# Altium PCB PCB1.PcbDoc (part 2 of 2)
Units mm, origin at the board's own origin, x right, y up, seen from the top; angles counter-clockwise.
Board outline 200 x 200.6 mm, 2 copper layers (Top Layer, Bottom Layer); 119 components, 156 nets, 629 pads, 125 vias.
Unrouted connection lines stored in the file: 2.
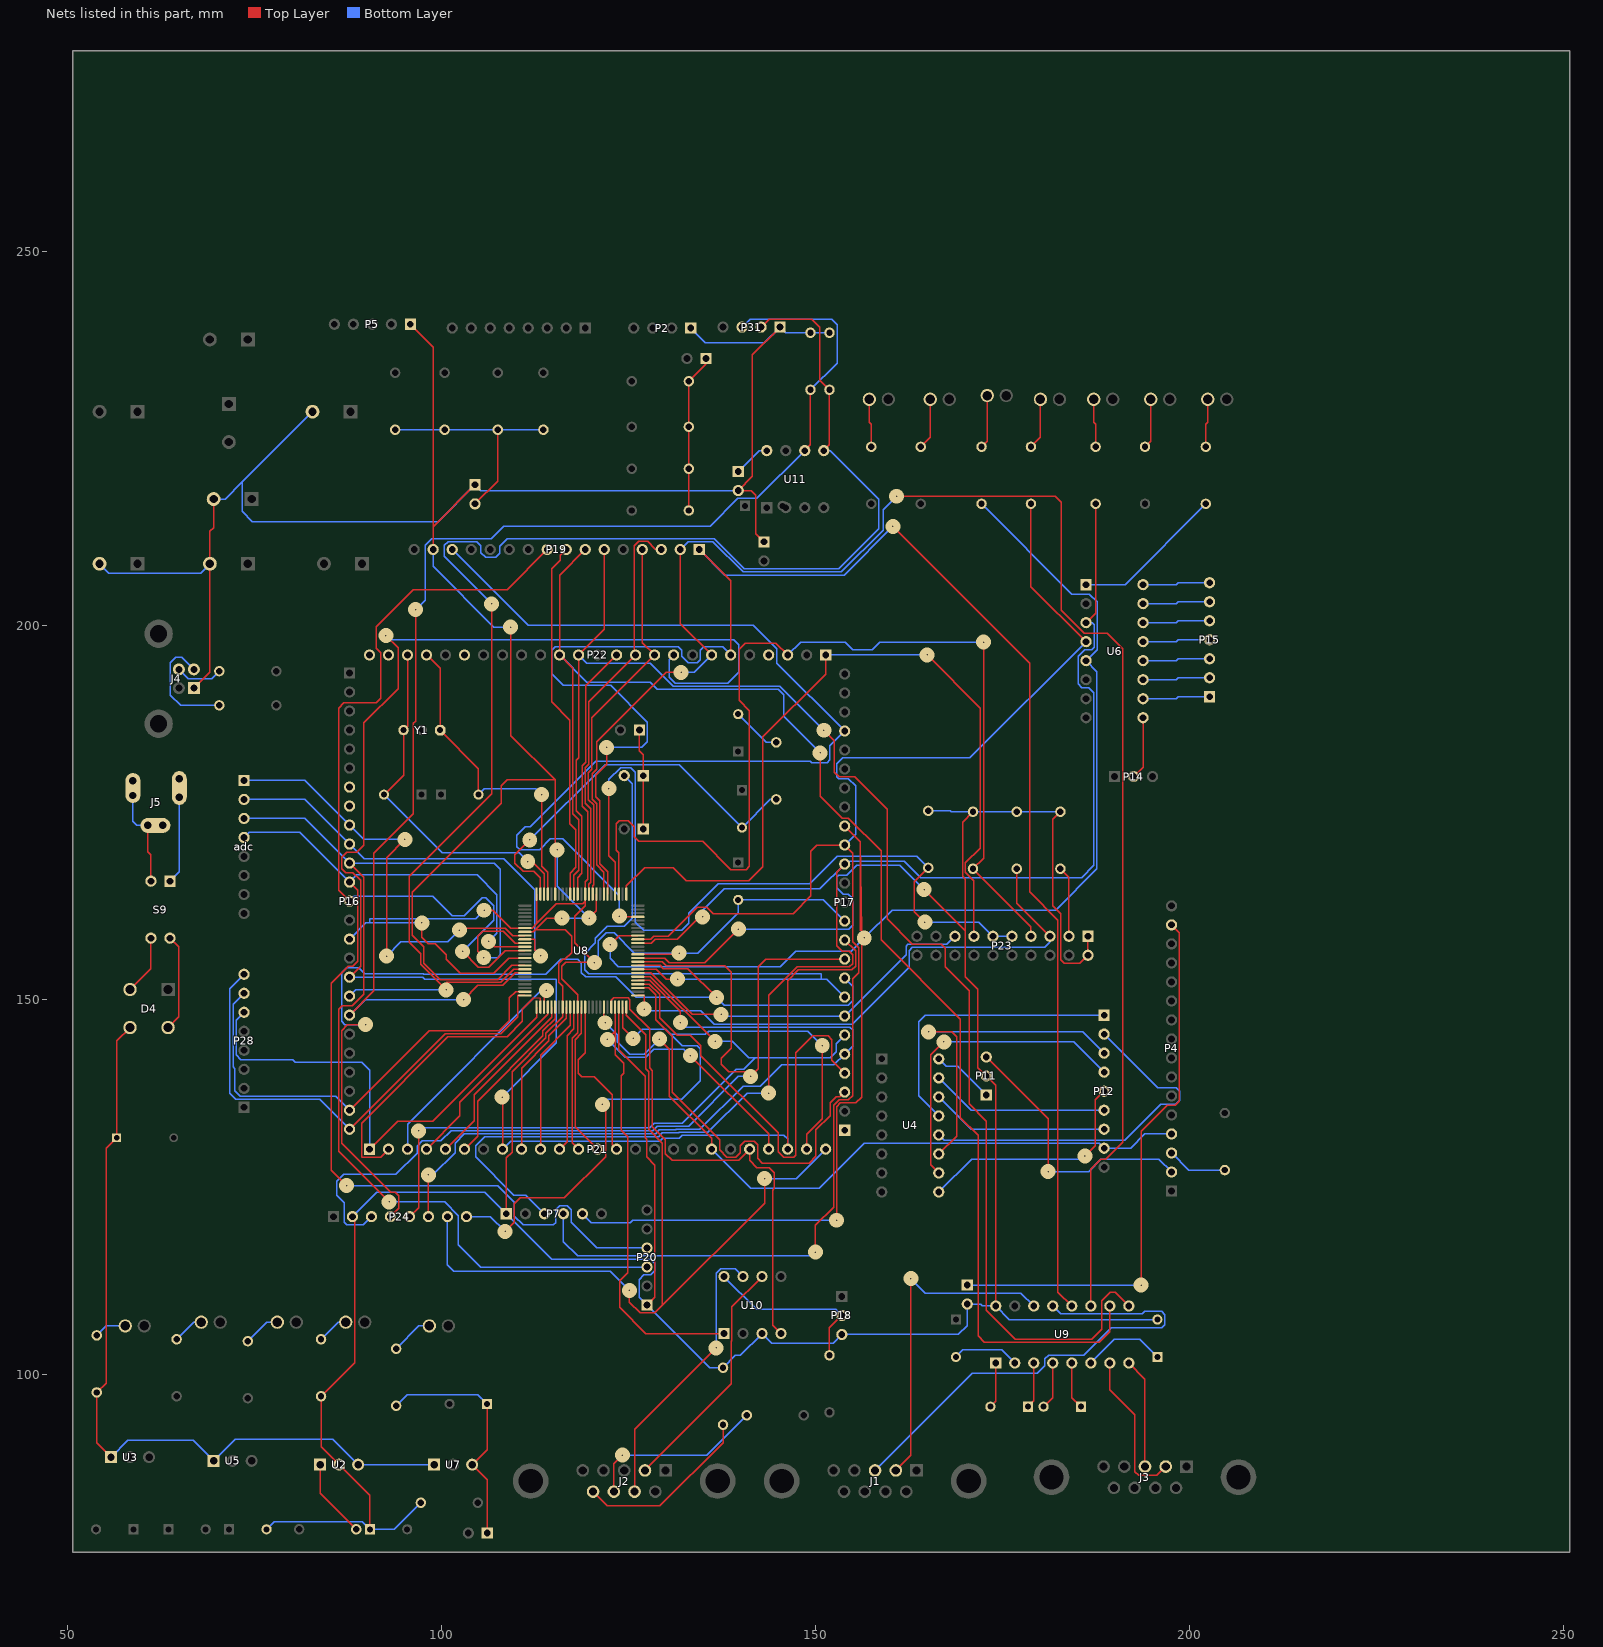
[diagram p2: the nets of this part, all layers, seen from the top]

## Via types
v1: diameter 2, hole 0.2, Top Layer to Bottom Layer, 125 vias

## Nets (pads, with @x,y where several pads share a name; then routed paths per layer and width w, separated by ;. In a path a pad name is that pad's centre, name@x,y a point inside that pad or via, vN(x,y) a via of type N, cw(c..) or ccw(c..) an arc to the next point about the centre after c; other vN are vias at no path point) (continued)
LED2: P7.3 P17.15 R19.1 U6.3 U8.65 | length 217.2
  Top Layer w0.2: U8.65@126.295,157.591 128.102,157.591 128.602,158.091 131.556,158.091 134.551,161.087 v1(134.925,161.087) ; v1(143.764,137.541) 143.764,150.597 147.565,154.398 154.534,154.398 154.974,154.838 154.974,156.058 154.534,156.498 153.619,156.498 152.857,157.26 152.857,167.081 P17.15@153.924,168.148 ; U6.3@186.182,200.406 187.452,201.676 R19.1@187.452,216.281
  Bottom Layer w0.2: P7.3@113.792,121.412 111.328,123.876 109.728,123.876 104.597,129.007 104.597,130.505 105.806,131.714 129.056,131.714 129.559,132.217 131.734,132.217 131.816,132.298 135.654,132.298 140.897,137.541 v1(143.764,137.541) ; v1(134.925,161.087) 134.925,161.95 137.82,164.846 150.622,164.846 P17.15@153.924,168.148 154.305,168.529 161.874,168.529 164.059,166.345 185.598,166.345 187.232,167.979 187.232,191.025 186.538,191.719 185.623,191.719 185.115,192.227 185.115,195.885 186.03,196.799 186.944,196.799 187.249,197.104 187.249,200.152 186.995,200.406 U6.3@186.182,200.406
LED3: P7.4 P17.16 R21.1 U6.4 U8.66 | length 208.6
  Top Layer w0.2: U8.66@126.295,158.091 128,158.091 128.4,158.491 130.34,158.491 134.254,162.405 135.464,162.405 136.346,161.523 147.02,161.523 149.398,163.902 149.398,169.875 150.211,170.688 P17.16@153.924,170.688 154.991,169.621 154.991,157.761 155.774,156.978 155.774,153.598 154.991,152.815 154.991,137.177 154.432,136.618 153.172,136.618 152.451,135.897 152.451,122.301 150.012,119.863 v1(150.012,116.281) ; R21.1@178.816,216.281 178.816,205.232 U6.4@186.182,197.866
  Bottom Layer w0.2: P7.4@116.332,121.412 116.332,117.685 118.244,115.773 149.504,115.773 v1(150.012,116.281) ; P17.16@153.924,170.688 155.397,172.161 155.397,178.613 154.432,179.578 153.128,179.578 152.874,179.832 152.874,181.525 153.67,182.321 170.637,182.321 U6.4@186.182,197.866
LED4: P7.5 P17.17 R22.1 U6.5 U8.67 | length 238.5
  Top Layer w0.2: v1(122.58,157.378) 123.793,158.591 U8.67@126.295,158.591 ; v1(152.857,120.548) 152.857,135.738 153.338,136.218 155.374,136.218 156.174,137.018 156.174,158.267 v1@156.174,159.142 ; P17.17@153.924,173.228 156.032,171.12 ; v1(156.54,158.267) 156.54,158.775 v1@156.174,159.142 ; 156.032,171.12 v1@156.174,159.142 ; 156.032,171.12 156.032,159.283 v1@156.174,159.142
  Bottom Layer w0.2: P7.5@118.872,121.412 120.04,120.244 125.273,120.244 125.578,120.548 v1(152.857,120.548) ; v1(122.58,157.378) 122.58,155.55 123.698,154.432 145.288,154.432 147.371,156.515 154.788,156.515 v1(156.54,158.267) 160.274,162.001 182.118,162.001 187.632,167.515 187.632,193.876 U6.5@186.182,195.326 187.655,196.799 187.655,203.2 186.639,204.216 184.277,204.216 R22.1@172.212,216.281
MISO: P16.24 P28.7 U8.24 | length 61.9
  Top Layer w0.2: P16.24@87.757,135.255 98.376,145.874 107.772,145.874 109.127,147.229 109.127,150.255 109.963,151.091 U8.24@111.195,151.091
  Bottom Layer w0.2: P28.7@73.66,150.876 72.187,149.403 72.187,141.072 72.441,140.818 72.441,137.837 73.152,137.126 85.886,137.126 P16.24@87.757,135.255
MOSI: P16.25 P28.8 U8.25 | length 67.2
  Top Layer w0.2: P16.25@87.757,132.715 100.516,145.474 107.975,145.474 110.24,147.738 110.24,150.591 U8.25@111.195,150.591
  Bottom Layer w0.2: P28.8@73.66,153.416 71.755,151.511 71.755,137.542 72.571,136.726 83.746,136.726 P16.25@87.757,132.715
NetC6_1: C6.1 P13.1 R26.1 U7.3 | length 32.2
  Top Layer w0.2: C6.1@106.132,96.012 106.132,89.876 U7.3@104.14,87.884 106.172,85.852 P13.1@106.172,78.74
  Bottom Layer w0.2: R26.1@93.98,95.758 95.453,97.231 104.913,97.231 C6.1@106.132,96.012
NetC9_2: C9.2 U9.2 | length 9
  Bottom Layer w0.2: C9.2@168.783,102.275 169.734,103.226 174.904,103.226 U9.2@176.657,101.473
NetC10_1: C10.1 U9.3 | length 6.2
  Top Layer w0.2: C10.1@178.395,95.631 179.197,96.433 U9.3@179.197,101.473
NetC10_2: C10.2 U9.1 | length 6.1
  Top Layer w0.2: C10.2@173.395,95.631 174.117,96.353 U9.1@174.117,101.473
NetC11_1: C11.1 U9.5 | length 6.4
  Top Layer w0.2: U9.5@184.277,101.473 184.277,96.861 C11.1@185.507,95.631
NetC11_2: C11.2 U9.4 | length 6.4
  Top Layer w0.2: C11.2@180.507,95.631 181.737,96.861 U9.4@181.737,101.473
NetC12_2: C12.2 R29.1 | length 6.6
  Bottom Layer w0.2: C12.2@139.7,188.174 143.47,184.404 R29.1@144.78,184.404
NetC13_2: C13.2 R29.2 U8.99 | length 52.4
  Top Layer w0.2: v1(111.836,171.374) 109.867,169.404 109.867,168.25 110.938,167.178 112.374,167.178 113.245,166.307 U8.99@113.245,164.141
  Bottom Layer w0.2: v1(111.836,171.374) 121.895,181.432 131.79,181.432 C13.2@140.208,173.014 143.978,176.784 R29.2@144.78,176.784
NetC14_1: C14.1 U9.6 | length 11.2
  Bottom Layer w0.2: U9.6@186.817,101.473 189.967,104.623 193.359,104.623 C14.1@195.707,102.275
NetD2_1: D2.1 R9.2 | length 4.2
  Bottom Layer w0.2: R9.2@83.947,104.648 86.233,106.934 D2.1@87.249,106.934
NetD3_1: D3.1 R14.2 | length 4.3
  Bottom Layer w0.2: R14.2@53.975,105.156 55.245,106.426 D3.1@57.785,106.426
NetD4_2: D4.2 S9.3 | length 8
  Top Layer w0.2: D4.2@58.42,151.384 61.214,154.178 S9.3@61.214,158.242
NetD4_4: D4.4 S9.4 | length 13
  Top Layer w0.2: D4.4@63.5,146.304 64.922,147.726 64.922,157.074 S9.4@63.754,158.242
NetD5_1: D5.1 R17.2 | length 6.5
  Top Layer w0.2: R17.2@202.184,223.901 202.184,226.949 202.438,227.203 D5.1@202.438,230.251
NetD6_1: D6.1 R18.2 | length 6.7
  Top Layer w0.2: R18.2@194.056,223.901 194.818,224.663 D6.1@194.818,230.251
NetD7_1: D7.1 R19.2 | length 6.5
  Top Layer w0.2: D7.1@187.198,230.251 187.198,227.203 187.452,226.949 R19.2@187.452,223.901
NetD8_1: D8.1 R21.2 | length 6.9
  Top Layer w0.2: R21.2@178.816,223.901 180.086,225.171 D8.1@180.086,230.251
NetD9_1: D9.1 R22.2 | length 7.2
  Top Layer w0.2: R22.2@172.212,223.901 172.974,224.663 D9.1@172.974,230.759
NetD10_1: D10.1 R23.2 | length 6.9
  Top Layer w0.2: R23.2@164.084,223.901 165.354,225.171 D10.1@165.354,230.251
NetD11_1: D11.1 R25.2 | length 6.5
  Top Layer w0.2: D11.1@157.226,230.251 157.226,227.203 157.48,226.949 R25.2@157.48,223.901
NetD12_1: D12.1 R24.2 | length 5
  Bottom Layer w0.2: R24.2@74.168,104.394 76.708,106.934 D12.1@78.105,106.934
NetD13_1: D13.1 R20.2 | length 4.2
  Bottom Layer w0.2: R20.2@64.643,104.648 66.929,106.934 D13.1@67.945,106.934
NetD14_1: D14.1 R26.2 | length 5.7
  Bottom Layer w0.2: R26.2@93.98,103.378 97.028,106.426 D14.1@98.425,106.426
NetJ1_2: J1.2 U9.14 | length 44.4
  Top Layer w0.2: J1.2@160.758,87.12 162.763,89.125 v1(162.763,112.751)
  Bottom Layer w0.2: v1(162.763,112.751) 164.694,110.82 177.47,110.82 U9.14@179.197,109.093
NetJ1_3: J1.3 U9.13 | length 64.4
  Bottom Layer w0.2: J1.3@157.988,87.12 170.944,100.076 179.629,100.076 180.67,101.117 180.67,102.006 181.204,102.54 185.903,102.54 189.56,106.197 196.291,106.197 196.698,106.604 196.698,107.95 196.291,108.356 194.031,108.356 193.7,108.026 182.804,108.026 U9.13@181.737,109.093
NetJ2_2: J2.2 U10.6 | length 32.4
  Top Layer w0.2: J2.2@127.23,87.12 138.786,98.676 138.786,104.369 138.862,104.445 138.862,109.017 U10.6@142.875,113.03
NetJ2_7: J2.7 U10.7 | length 38
  Top Layer w0.2: J2.7@125.845,84.28 125.845,92.596 v1(136.728,103.48)
  Bottom Layer w0.2: v1(136.728,103.48) 136.728,113.462 137.363,114.097 139.268,114.097 U10.7@140.335,113.03
NetJ2_8: J2.8 R28.1 | length 24.2
  Top Layer w0.2: J2.8@123.075,84.28 123.075,87.998 v1(124.231,89.154)
  Bottom Layer w0.2: v1(124.231,89.154) 135.509,89.154 R28.1@140.843,94.488
NetJ2_9: J2.9 R27.1 | length 24.1
  Top Layer w0.2: J2.9@120.305,84.28 122.213,82.372 129.235,82.372 137.668,90.805 R27.1@137.668,93.218
NetJ3_2: J3.2 U9.7 | length 20.7
  Top Layer w0.2: U9.7@189.357,101.473 189.357,97.866 192.684,94.539 192.684,86.97 193.192,86.462 195.66,86.462 J3.2@196.826,87.628
NetJ3_3: J3.3 U9.8 | length 14.7
  Top Layer w0.2: U9.8@191.897,101.473 194.056,99.314 J3.3@194.056,87.628
NetJ4_2: J4.2 R31.1 | length 15.5
  Bottom Layer w0.2: J4.2@66.953,194.163 65.333,195.783 64.541,195.783 63.83,195.072 63.83,190.729 65.202,189.357 R31.1@70.358,189.357
NetJ4_3: J4.3 R32.1 | length 6.4
  Bottom Layer w0.2: J4.3@64.953,194.163 66.228,192.888 69.317,192.888 R32.1@70.358,193.929
NetJ5_1: J5.1 J5.1A J5.1B S9.1 | length 15.5
  Top Layer w0.2: J5.1A@65.008,177.058 J5.1@65.008,178.308 J5.1B@65.008,179.558
  Bottom Layer w0.2: S9.1@63.754,165.862 65.008,167.116 J5.1A@65.008,177.058 J5.1@65.008,178.308
NetJ5_2: J5.2 J5.2A J5.2B J5.3 J5.3A J5.3B S9.2 | length 18.3
  Top Layer w0.2: J5.2A@58.808,177.308 J5.2@58.808,178.308 J5.2B@58.808,179.308 ; J5.3A@60.808,173.308 60.808,169.773 61.214,169.367 S9.2@61.214,165.862
  Bottom Layer w0.2: J5.2@58.808,178.308 J5.2A@58.808,177.308 58.808,173.834 59.334,173.308 J5.3A@60.808,173.308 J5.3@61.808,173.308 J5.3B@62.808,173.308
NetP1_2: P1.2 R1.2 R2.2 R3.2 R4.2 | length 31
  Top Layer w0.2: P1.2@104.521,216.281 107.569,219.329 R2.2@107.569,226.187
  Bottom Layer w0.2: R4.2@93.853,226.187 R3.2@100.457,226.187 R2.2@107.569,226.187 R1.2@113.665,226.187
NetP4_2: P4.2 P11.3 | length 36.6
  Top Layer w0.2: P11.3@172.847,142.367 181.102,134.112 v1(181.102,127.051)
  Bottom Layer w0.2: v1(181.102,127.051) 186.526,127.051 188.16,128.685 195.927,128.685 P4.2@197.612,127
NetP4_3: P4.3 R8.1 | length 8.1
  Bottom Layer w0.2: P4.3@197.612,129.54 199.898,127.254 R8.1@204.724,127.254
NetP4_15: P4.15 P10.1 | length 74.5
  Top Layer w0.2: v1(193.548,111.887) 193.548,132.41 197.028,135.89 198.069,135.89 198.662,136.483 198.662,158.97 P4.15@197.612,160.02
  Bottom Layer w0.2: P10.1@170.307,111.887 v1(193.548,111.887)
NetP8_1: P8.1 R10.1 R11.1 R12.1 R13.1 | length 21.3
  Top Layer w0.2: R10.1@133.096,215.392 R11.1@133.096,220.98 R12.1@133.096,226.568 R13.1@133.096,232.664 135.382,234.95 P8.1@135.382,235.712
NetP11_1: P11.1 U4.16 | length 8.3
  Bottom Layer w0.2: U4.16@166.497,142.113 167.488,141.122 169.012,141.122 P11.1@172.847,137.287
NetP12_1: P12.1 U4.13 | length 38.8
  Bottom Layer w0.2: U4.13@166.497,134.493 163.805,137.185 163.805,147.041 164.719,147.955 P12.1@188.595,147.955
NetP12_2: P12.2 U4.12 | length 49.1
  Bottom Layer w0.2: U4.12@166.497,131.953 167.21,131.24 191.318,131.24 196.148,136.07 198.198,136.07 198.679,136.55 198.679,137.77 198.222,138.227 195.783,138.227 P12.2@188.595,145.415
NetP12_3: P12.3 U4.11 | length 45.3
  Top Layer w0.2: v1(165.125,145.72) 168.25,145.72 168.885,145.085 168.885,131.801 U4.11@166.497,129.413
  Bottom Layer w0.2: v1(165.125,145.72) 185.75,145.72 P12.3@188.595,142.875
NetP12_4: P12.4 U4.10 | length 41.8
  Top Layer w0.2: U4.10@166.497,126.873 165.43,127.94 165.43,142.646 v1(167.183,144.399)
  Bottom Layer w0.2: v1(167.183,144.399) 184.531,144.399 P12.4@188.595,140.335
NetP12_5: P12.5 U4.9 | length 31.2
  Top Layer w0.2: v1(186.03,129.134) 187.427,130.531 187.427,136.627 P12.5@188.595,137.795
  Bottom Layer w0.2: U4.9@166.497,124.333 170.891,128.727 185.623,128.727 v1(186.03,129.134)
NetP12_6: P12.6 U4.15 | length 23.9
  Bottom Layer w0.2: U4.15@166.497,139.573 170.815,135.255 P12.6@188.595,135.255
NetP12_7: P12.7 U4.14 | length 23.9
  Bottom Layer w0.2: U4.14@166.497,137.033 170.815,132.715 P12.7@188.595,132.715
NetP14_2: P14.2 U6.9 | length 8.4
  Top Layer w0.2: P14.2@192.532,179.832 193.802,181.102 U6.9@193.802,187.706
NetP15_1: P15.1 U6.10 | length 9
  Bottom Layer w0.2: U6.10@193.802,190.246 198.247,190.246 198.501,190.5 P15.1@202.692,190.5
NetP15_2: P15.2 U6.11 | length 9
  Bottom Layer w0.2: U6.11@193.802,192.786 198.247,192.786 198.501,193.04 P15.2@202.692,193.04
NetP15_3: P15.3 U6.12 | length 9
  Bottom Layer w0.2: U6.12@193.802,195.326 198.247,195.326 198.501,195.58 P15.3@202.692,195.58
NetP15_4: P15.4 U6.13 | length 9
  Bottom Layer w0.2: U6.13@193.802,197.866 198.247,197.866 198.501,198.12 P15.4@202.692,198.12
NetP15_5: P15.5 U6.14 | length 9
  Bottom Layer w0.2: U6.14@193.802,200.406 198.247,200.406 198.501,200.66 P15.5@202.692,200.66
NetP15_6: P15.6 U6.15 | length 9
  Bottom Layer w0.2: U6.15@193.802,202.946 198.247,202.946 198.501,203.2 P15.6@202.692,203.2
NetP15_7: P15.7 U6.16 | length 9
  Bottom Layer w0.2: U6.16@193.802,205.486 198.247,205.486 198.501,205.74 P15.7@202.692,205.74
NetP18_2: P18.2 R30.2 U10.8 | length 23.9
  Top Layer w0.2: R30.2@151.892,102.489 151.892,106.172 P18.2@153.543,107.823
  Bottom Layer w0.2: U10.8@137.795,113.03 142.189,108.636 152.73,108.636 P18.2@153.543,107.823
NetP23_3: P23.3 R36.1 | length 9.5
  Top Layer w0.2: R36.1@182.753,167.513 183.896,166.37 P23.3@183.896,158.496
NetP23_5: P23.5 R35.1 U8.51 | length 75.2
  Top Layer w0.2: U8.51@126.295,150.591 127.127,150.591 v1(127.127,148.768) ; R35.1@176.911,167.513 176.911,162.941 P23.5@181.356,158.496
  Bottom Layer w0.2: v1(127.127,148.768) 127.356,148.539 134.717,148.539 136.5,146.757 154.944,146.757 162.526,154.339 162.526,156.566 162.966,157.006 180.679,157.006 181.356,157.683 P23.5@181.356,158.496
NetP23_9: P23.9 P23.11 R33.1 U8.79 | length 106.3
  Top Layer w0.2: v1(122.403,178.232) 122.403,169.244 123.245,168.402 U8.79@123.245,164.141 ; v1(164.643,160.376) 163.22,161.798 163.22,165.76 R33.1@165.1,167.64
  Bottom Layer w0.2: v1(122.403,178.232) 122.403,179.451 123.977,181.026 125.349,181.026 125.933,180.442 125.933,160.401 127.051,159.283 132.14,159.283 133.101,160.244 133.101,161.56 137.06,165.52 149.242,165.52 152.921,169.198 163.542,169.198 R33.1@165.1,167.64 ; v1(164.643,160.376) 171.856,160.376 P23.11@173.736,158.496 P23.9@176.276,158.496
NetP27_1: P27.1 P30.1 P33.1 | length 13.4
  Top Layer w0.2: P33.1@126.492,186.055 126.492,183.261 127,182.753 P27.1@127,179.959 P30.1@127,172.847
NetP32_1: P32.1 U11.8 | length 5
  Bottom Layer w0.2: P32.1@139.7,220.599 142.494,223.393 U11.8@143.51,223.393
NetR15_2: R15.2 U2.1 | length 10.6
  Top Layer w0.2: U2.1@83.82,87.884 83.82,84.074 R15.2@88.646,79.248
NetR17_1: R17.1 U6.1 | length 20.5
  Bottom Layer w0.2: U6.1@186.182,205.486 191.389,205.486 R17.1@202.184,216.281
NRST: P17.7 P23.15 U8.57 | length 49.8
  Top Layer w0.2: U8.57@126.295,153.591 128.021,153.591 133.555,148.057 v1(137.414,148.057)
  Bottom Layer w0.2: v1(137.414,148.057) 137.643,147.828 P17.7@153.924,147.828 162.126,156.03 162.126,157.175 162.357,157.406 167.566,157.406 P23.15@168.656,158.496
PA0/PGMEN0/RXD0: P19.1 P22.6 U8.81 U9.12 | length 235.3
  Top Layer w0.2: v1(122.098,183.744) 122.098,181.467 120.629,179.998 120.629,177.175 121.195,176.609 121.195,168.198 122.245,167.148 U8.81@122.245,164.141 ; P19.1@134.493,210.185 138.684,205.994 P22.6@138.684,196.088 ; v1(160.376,213.258) 178.638,194.996 178.638,164.44 182.423,160.655 182.423,110.947 U9.12@184.277,109.093
  Bottom Layer w0.2: v1(122.098,183.744) 126.797,183.744 127.559,184.506 127.559,187.122 122.657,192.024 116.307,192.024 114.757,193.573 114.757,196.698 115.214,197.155 131.674,197.155 132.131,196.698 132.131,195.91 133.003,195.038 134.214,195.038 134.654,195.478 134.654,196.698 135.111,197.155 137.617,197.155 P22.6@138.684,196.088 ; P19.1@134.493,210.185 137.922,206.756 153.873,206.756 v1(160.376,213.258)
PA1/PGMEN1/TXD0: P19.2 P22.7 U8.82 U9.11 | length 231.1
  Top Layer w0.2: U8.82@121.745,164.141 121.745,167.08 120.795,168.03 120.795,176.209 120.18,176.823 120.18,180.208 120.766,180.794 120.766,184.469 130.048,193.751 v1(132.08,193.751) ; P19.2@131.953,210.185 131.953,200.279 P22.7@136.144,196.088 ; v1(160.858,217.297) 182.067,217.297 182.88,216.484 182.88,202.032 185.928,198.984 189.027,198.984 191.059,196.952 191.059,130.962 188.781,128.685 188.16,128.685 186.817,127.342 U9.11@186.817,109.093
  Bottom Layer w0.2: P19.2@131.953,210.185 133.003,211.235 136.306,211.235 140.353,207.188 153.492,207.188 159.055,212.75 159.055,215.494 v1(160.858,217.297) ; v1(132.08,193.751) 133.807,193.751 P22.7@136.144,196.088
"PA2 3/PGMD11/TD": P17.5 P24.6 U8.55 | length 104.7
  Top Layer w0.2: P24.6@98.298,121.031 v1(98.298,126.619) ; U8.55@126.295,152.591 127.89,152.591 131.978,148.502 v1(131.978,146.964)
  Bottom Layer w0.2: v1(98.298,126.619) 98.908,126.619 101.854,129.565 101.854,130.861 103.107,132.114 128.656,132.114 129.159,132.617 131.334,132.617 131.416,132.698 134.578,132.698 140.356,138.476 142.651,138.476 145.481,141.307 152.483,141.307 P17.5@153.924,142.748 154.991,143.815 154.991,145.999 154.633,146.357 132.586,146.357 v1(131.978,146.964)
PA2/SCK0: P19.3 P22.11 U8.86 | length 54.1
  Top Layer w0.2: U8.86@119.745,164.141 119.745,165.45 119.995,165.7 119.995,175.56 119.268,176.287 119.268,181.026 119.742,181.5 119.742,189.846 P22.11@125.984,196.088 125.806,196.266 125.806,210.668 126.39,211.252 127.61,211.252 128.575,210.287 128.575,210.185 P19.3@129.413,210.185
PA3/RTS0: P19.4 P22.10 U8.85 | length 50.8
  Top Layer w0.2: U8.85@120.245,164.141 120.245,165.235 120.395,165.385 120.395,176.043 119.668,176.77 119.668,180.374 120.142,180.848 120.142,187.706 P22.10@128.524,196.088 126.873,197.739 P19.4@126.873,210.185
"PA5/PGMRDY/RX D 1": P19.6 P22.14 U8.89 U9.9 | length 201.3
  Top Layer w0.2: U8.89@118.245,164.141 118.245,166.35 118.795,166.9 118.795,174.518 118.028,175.285 118.028,182.016 118.364,182.352 P22.14@118.364,196.088 121.793,199.517 P19.6@121.793,210.185 ; v1(151.13,186.03) 152.527,184.633 152.527,180.442 153.187,179.781 155.245,179.781 159.58,175.446 159.58,160.816 162.966,157.429 166.827,157.429 167.386,156.87 167.386,154.405 170.561,151.23 170.561,136.119 172.872,133.807 172.872,108.509 176.712,104.669 186.969,104.669 188.29,105.99 188.29,109.804 189.382,110.896 190.094,110.896 U9.9@191.897,109.093
  Bottom Layer w0.2: P22.14@118.364,196.088 119.482,194.97 127.948,194.97 130.989,191.928 145.231,191.928 v1(151.13,186.03)
"PA6/PGMNOE/T X D1": P19.7 P22.15 U8.90 U9.10 | length 199.8
  Top Layer w0.2: U8.90@117.745,164.141 117.745,166.65 118.395,167.3 118.395,174.06 117.594,174.861 117.594,194.318 P22.15@115.824,196.088 115.824,206.756 P19.7@119.253,210.185 ; v1(150.647,183.007) 150.647,177.241 153.594,174.295 154.432,174.295 158.78,169.947 158.78,158.009 169.393,147.396 169.393,134.264 171.78,131.877 171.78,105.08 172.593,104.267 187.96,104.267 189.357,105.664 U9.10@189.357,109.093
  Bottom Layer w0.2: P22.15@115.824,196.088 119.482,192.43 127.969,192.43 128.871,191.528 145.024,191.528 145.779,190.773 145.779,187.875 v1(150.647,183.007)
PA7/PGMNVALID/SCK1: P19.8 U8.91 | length 48.5
  Top Layer w0.2: P19.8@116.713,210.185 115.913,209.385 115.913,208.735 114.757,207.579 114.757,189.809 117.194,187.373 117.194,173.501 117.995,172.7 117.995,167.7 117.245,166.95 U8.91@117.245,164.141
PA8/PGMM0/RTS1: P16.13 P19.9 U8.13 | length 109.5
  Top Layer w0.2: P16.13@87.757,163.195 86.307,164.645 86.307,188.999 86.993,189.685 91.311,189.685 91.897,190.271 91.897,196.384 91.308,196.972 91.308,199.869 96.265,204.826 108.814,204.826 P19.9@114.173,210.185 ; v1(102.87,156.464) 104.983,154.351 106.351,154.351 108.591,156.591 U8.13@111.195,156.591
  Bottom Layer w0.2: P16.13@87.757,163.195 88.392,163.83 98.857,163.83 101.452,161.235 103.094,161.235 105.486,163.627 105.969,163.627 107.036,162.56 107.036,160.63 v1(102.87,156.464)
"PA10/PGMM2/TW D": P16.18 P31.2 R37.1 U8.18 U11.5 | length 199.5
  Top Layer w0.2: v1(106.756,202.921) 106.756,177.546 95.707,166.497 95.707,157.713 97.255,156.166 97.255,154.739 v1(100.66,151.333) 100.66,152.319 107.955,152.319 109.726,154.091 U8.18@111.195,154.091 ; P31.2@142.748,239.903 143.815,240.97 149.555,240.97 150.622,239.903 150.622,232.791 R37.1@151.892,231.521 151.892,224.155 U11.5@151.13,223.393
  Bottom Layer w0.2: P16.18@87.757,150.495 88.595,151.333 v1(100.66,151.333) ; v1(106.756,202.921) 100.406,209.271 100.406,210.718 100.923,211.235 104.741,211.235 105.283,210.693 105.283,209.779 105.943,209.118 107.29,209.118 107.823,209.652 107.823,210.642 108.816,211.635 136.472,211.635 140.513,207.594 153.111,207.594 158.496,212.979 158.496,216.891 151.994,223.393 U11.5@151.13,223.393
"PA11/PGMM3/TW CK": P16.19 P31.3 R38.1 U8.19 U11.6 | length 180.8
  Top Layer w0.2: P16.19@87.757,147.955 91.004,151.202 91.004,169.591 96.291,174.879 96.291,186.944 96.594,187.247 v1(96.594,202.159) ; v1(102.99,150.033) 104.876,151.919 108.231,151.919 109.903,153.591 U8.19@111.195,153.591 ; U11.6@148.59,223.393 149.352,224.155 R38.1@149.352,231.521
  Bottom Layer w0.2: P16.19@87.757,147.955 89.835,150.033 v1(102.99,150.033) ; v1(96.594,202.159) 97.866,203.431 97.866,210.752 98.749,211.635 106.711,211.635 108.385,213.309 135.956,213.309 139.649,217.002 142.199,217.002 U11.6@148.59,223.393 ; P31.3@140.208,239.903 141.275,240.97 152.171,240.97 152.908,240.233 152.908,235.077 R38.1@149.352,231.521
PA18/PGMD6/SPI0_SPCK: P21.1 P28.6 U8.26 | length 66.4
  Top Layer w0.2: P21.1@90.424,130.048 94.173,133.797 98.887,133.797 112.745,147.656 U8.26@112.745,149.041
  Bottom Layer w0.2: P28.6@73.66,148.336 72.593,147.269 72.593,142.646 73.228,142.011 80.137,142.011 80.518,141.63 89.408,141.63 90.424,140.614 P21.1@90.424,130.048
PA19/PGMD7/CANRX: P21.21 U8.46 U10.4 | length 65.9
  Top Layer w0.2: U8.46@122.745,149.041 122.745,149.962 123.05,150.266 124.968,150.266 125.197,150.038 125.197,148.768 127.844,146.12 127.844,140.906 128.232,140.519 128.232,133.032 129.974,131.289 129.974,129.462 130.861,128.575 139.751,128.575 P21.21@141.224,130.048 141.224,128.548 142.191,127.581 143.866,127.581 144.541,126.906 144.541,124.803 144.325,124.587 144.325,106.5 U10.4@145.415,105.41
PA20/PGMD8/CANTX: P21.22 U8.47 U10.1 | length 88.1
  Top Layer w0.2: v1(122.199,144.729) 123.245,145.775 ; U8.47@123.245,149.041 123.245,145.775 ; v1(133.299,142.545) 143.764,132.08 P21.22@143.764,130.048 ; U10.1@137.795,105.41 127.346,105.41 123.841,108.915 123.841,112.47 124.917,113.546 124.917,131.699 124.054,132.563 124.054,139.852 124.384,140.183 124.384,141.508 123.245,142.646 123.245,144.729 123.245,145.775
  Bottom Layer w0.2: v1(122.199,144.729) 124.585,142.343 127.354,142.343 128.417,143.407 132.437,143.407 v1(133.299,142.545)
PA21/PGMD9/TF: P21.24 P24.8 U8.49 | length 102
  Top Layer w0.2: v1(108.547,119.062) 109.779,120.294 109.779,122.733 110.592,123.546 116.459,123.546 121.971,129.057 121.971,135.611 v1(121.539,136.042) ; U8.49@124.245,149.041 124.245,146.265 v1(125.654,144.856) ; P21.24@148.844,130.048 148.844,132.029 150.927,134.112 v1(150.927,143.891)
  Bottom Layer w0.2: P24.8@103.378,121.031 106.578,121.031 v1(108.547,119.062) ; v1(121.539,136.042) 122.229,136.733 132.135,136.733 134.62,139.217 134.62,143.459 134.214,143.866 132.232,143.866 130.704,145.394 ; v1(125.654,144.856) 126.852,146.055 130.043,146.055 130.704,145.394 ; v1(150.927,143.891) 148.987,145.831 135.738,145.831 135.301,145.394 130.704,145.394
PA22/PGMD10/TK: P21.25 P24.7 U8.50 | length 113.4
  Top Layer w0.2: U8.50@124.745,149.041 124.745,147.924 127.356,145.313 127.356,140.767 127.711,140.411 127.711,132.724 129.574,130.861 129.574,109.178 ; v1(125.146,111.176) 125.146,109.618 126.594,108.17 128.566,108.17 129.57,109.174 ; v1(143.231,126.111) 143.231,122.834 129.574,109.178 ; 129.57,109.174 129.574,109.178 ; 129.57,109.174 129.574,109.169 129.574,109.178
  Bottom Layer w0.2: P24.7@100.838,121.031 100.838,114.605 101.702,113.741 122.58,113.741 v1(125.146,111.176) ; v1(143.231,126.111) 147.447,126.111 P21.25@151.384,130.048
PA24/PGMD12/RD: P17.6 P24.5 U8.56 | length 95
  Top Layer w0.2: P24.5@95.758,121.031 96.977,122.25 v1(96.977,132.486) ; U8.56@126.295,153.091 127.955,153.091 v1(136.601,144.445)
  Bottom Layer w0.2: v1(96.977,132.486) 97.411,132.92 127.862,132.92 128.47,133.528 132.232,133.528 139.421,140.716 140.441,140.716 141.965,142.24 ; v1(136.601,144.445) 138.901,144.445 141.106,142.24 141.965,142.24 ; P17.6@153.924,145.288 152.781,144.145 152.781,143.053 151.968,142.24 141.965,142.24
PA25/PGMD13/RK: P17.9 P24.4 U8.59 | length 131.4
  Top Layer w0.2: v1(89.916,146.685) 87.478,146.685 86.69,145.898 86.69,130.852 93.261,124.281 93.878,124.281 94.345,123.815 94.345,122.158 P24.4@93.218,121.031 ; U8.59@126.295,154.591 129.266,154.591 129.701,154.156 132.976,154.156 v1(136.81,150.322)
  Bottom Layer w0.2: v1(89.916,146.685) 87.122,146.685 86.69,147.117 86.69,153.619 87.376,154.305 88.98,154.305 89.803,153.482 97.6,153.482 97.665,153.418 113.987,153.418 115.967,155.397 118.262,155.397 118.745,154.915 118.745,153.619 119.304,153.06 123.317,153.06 126.06,150.317 v1@136.81,150.317 ; v1(136.81,150.322) v1@136.81,150.317 ; P17.9@153.924,152.908 154.991,151.841 154.991,149.86 154.432,149.301 137.831,149.301 v1@136.81,150.317
PA26/PGMD14/RF: P17.10 P24.3 U8.60 | length 129.6
  Top Layer w0.2: U8.60@126.295,155.091 129.566,155.091 130.101,154.556 137.898,154.556 138.735,153.719 138.735,143.535 137.414,142.215 137.414,141.427 138.455,140.386 141.351,140.386 v1(141.351,139.776) 142.342,140.767 142.342,154.432 143.358,155.448 P17.10@153.924,155.448
  Bottom Layer w0.2: P24.3@90.678,121.031 89.611,119.964 87.376,119.964 87.071,120.269 87.071,122.876 86.063,123.884 86.063,125.776 86.97,126.682 93.942,126.682 96.774,129.515 96.774,130.454 97.46,131.14 99.949,131.14 101.329,132.52 128.262,132.52 128.863,133.121 133.071,133.121 139.725,139.776 v1(141.351,139.776)
PB4/ECRS: P17.4 U8.54 | length 59.6
  Top Layer w0.2: U8.54@126.295,152.091 127.824,152.091 129.178,150.737 129.178,147.638 131.535,145.281 133.269,145.281 134.704,143.845 134.704,142.545 145.034,132.215 145.034,129.718 145.754,128.998 147.117,128.998 147.354,129.235 147.354,142.918 149.627,145.191 151.714,145.191 152.227,144.678 152.227,141.905 P17.4@153.924,140.208
PB5/ERX0: P21.9 U8.34 | length 21.5
  Top Layer w0.2: P21.9@110.744,130.048 110.744,140.886 114.409,144.551 114.409,145.203 116.745,147.539 U8.34@116.745,149.041
PB6/ERX1: P21.6 U8.31 | length 24
  Top Layer w0.2: P21.6@103.124,130.048 104.88,131.804 104.88,136.446 113.609,145.175 113.609,145.846 115.245,147.482 U8.31@115.245,149.041
PB7/ERXER: P21.13 U8.38 | length 20.6
  Top Layer w0.2: U8.38@118.745,149.041 118.745,145.517 117.909,144.68 117.909,133.043 P21.13@120.904,130.048
PB8/EMDC: P21.3 U8.28 | length 31.7
  Top Layer w0.2: U8.28@113.745,149.041 113.745,150.931 v1(114.071,151.257)
  Bottom Layer w0.2: P21.3@95.504,130.048 95.504,133.391 113.37,151.257 v1(114.071,151.257)
PB9/EMDIO: P21.2 U8.27 | length 41.6
  Top Layer w0.2: P21.2@92.964,130.048 91.897,128.981 89.357,128.981 89.357,133.528 100.903,145.074 108.799,145.074 110.868,147.143 110.868,148.739 112.395,150.266 113.245,150.241 U8.27@113.245,149.041
PB10/ETX2: P4.4 P12.8 P21.19 U8.44 | length 97.3
  Top Layer w0.2: U8.44@121.745,149.041 121.745,147.114 v1(121.92,146.939) ; v1(129.159,144.755) 130.484,143.429 130.484,137.133 136.144,131.473 P21.19@136.144,130.048
  Bottom Layer w0.2: v1(121.92,146.939) 123.541,145.318 123.541,144.374 125.171,142.743 127.148,142.743 v1(129.159,144.755) ; P21.19@136.144,130.048 141.389,124.803 150.533,124.803 156.57,130.84 187.93,130.84 P12.8@188.595,130.175 192.151,130.175 194.056,132.08 P4.4@197.612,132.08
PB12/ETXER: P21.14 U8.39 | length 22.5
  Top Layer w0.2: U8.39@119.245,149.041 119.245,142.922 118.309,141.986 118.309,140.208 118.796,139.721 120.451,139.721 122.839,137.333 122.839,130.653 P21.14@123.444,130.048
PB13/ERX2: P21.5 U8.30 | length 24.9
  Top Layer w0.2: P21.5@100.584,130.048 104.411,133.875 104.411,137.316 114.745,147.65 U8.30@114.745,149.041
PB14/ERX3: P21.4 U8.29 | length 25.7
  Top Layer w0.2: P21.4@98.044,130.048 102.498,134.502 102.498,136.32 114.245,148.066 U8.29@114.245,149.041
PB15/ERXDV/ECRSDV: P21.10 U8.35 | length 20.6
  Top Layer w0.2: P21.10@113.284,130.048 113.284,142.626 117.245,146.587 U8.35@117.245,149.041
PB16/ECOL: P17.3 U8.53 | length 54.8
  Top Layer w0.2: U8.53@126.295,151.591 127.758,151.591 128.688,150.661 128.688,147.327 130.884,145.131 130.884,137.661 137.211,131.334 137.211,129.946 138.176,128.981 139.395,128.981 139.954,129.54 139.954,130.505 140.547,131.098 141.834,131.098 142.274,130.658 142.274,128.829 142.905,128.198 149.178,128.198 150.089,129.108 150.089,132.642 151.992,134.545 151.992,136.224 152.806,137.039 153.295,137.039 P17.3@153.924,137.668
PB17/ERXCK: P21.11 U8.36 | length 19.8
  Top Layer w0.2: P21.11@115.824,130.048 116.816,131.04 116.816,145.197 117.745,146.126 U8.36@117.745,149.041
PB26/TIOB1: P17.22 P19.14 U8.72 | length 138.8
  Top Layer w0.2: v1(123.825,161.188) 123.922,161.091 U8.72@126.295,161.091
  Bottom Layer w0.2: P19.14@101.473,210.185 111.608,200.05 141.707,200.05 144.854,196.903 144.854,194.998 P17.22@153.924,185.928 151.947,183.951 151.947,182.067 151.587,181.707 149.53,181.707 149.347,181.889 120.675,181.889 111.912,173.126 111.227,173.126 110.13,172.03 110.13,170.464 110.541,170.053 113.145,170.053 114.592,171.5 116.23,171.5 123.825,163.906 v1(123.825,161.188)
PB27/AD0/TIOA2: adc.1 P16.9 U8.9 | length 61.8
  Top Layer w0.2: v1(92.71,155.854) 92.71,169.012 v1(95.148,171.45) ; v1(102.438,159.309) 102.716,159.586 108.591,159.586 109.586,158.591 U8.9@111.195,158.591
  Bottom Layer w0.2: adc.1@73.66,179.324 81.788,179.324 P16.9@87.757,173.355 89.662,171.45 v1(95.148,171.45) ; v1(92.71,155.854) 94.616,157.761 100.89,157.761 v1(102.438,159.309)
PB28/AD1/TIOB2: adc.2 P16.10 U8.10 | length 56.8
  Top Layer w0.2: U8.10@111.195,158.091 112.444,158.091 112.492,158.043 112.492,156.672 v1(113.284,155.88)
  Bottom Layer w0.2: adc.2@73.66,176.784 81.788,176.784 P16.10@87.757,170.815 89.713,168.859 108.38,168.859 112.492,164.747 112.492,156.672 v1(113.284,155.88)
PB29/AD2/PCK1: adc.3 P16.11 P20.3 U8.11 | length 152.7
  Top Layer w0.2: P16.11@87.757,168.275 89.624,166.408 89.624,150.762 88.087,149.225 86.766,149.225 86.284,148.742 86.284,129.743 v1(93.04,122.987) ; v1(105.689,155.651) 104.877,156.464 104.877,158.496 105.567,159.186 108.301,159.186 109.896,157.591 U8.11@111.195,157.591
  Bottom Layer w0.2: adc.3@73.66,174.244 81.788,174.244 P16.11@87.757,168.275 107.086,168.275 107.925,167.437 107.925,156.032 107.544,155.651 v1(105.689,155.651) ; v1(93.04,122.987) 100.457,122.987 102.311,121.133 102.311,117.272 105.283,114.3 P20.3@127.508,114.3
PB30/AD3/PCK2: adc.4 P16.12 P20.4 U8.12 | length 142.6
  Top Layer w0.2: v1(87.363,125.184) 85.293,127.254 85.293,152.222 87.579,154.508 88.189,154.508 88.824,155.143 88.824,164.668 P16.12@87.757,165.735 ; v1(106.35,157.81) 107.069,157.091 U8.12@111.195,157.091
  Bottom Layer w0.2: adc.4@73.66,171.704 74.377,172.421 81.071,172.421 P16.12@87.757,165.735 88.722,166.7 104.8,166.7 107.442,164.059 107.442,158.902 v1(106.35,157.81) ; v1(87.363,125.184) 107.531,125.184 109.779,122.936 109.779,121.107 110.966,119.92 115.011,119.92 115.282,120.191 115.282,121.92 115.824,122.462 116.84,122.462 117.382,121.92 117.382,120.26 120.802,116.84 P20.4@127.508,116.84
PLLRC: P22.24
TCK: P22.4
TDI: P17.1
TDO: P22.1 P23.13 U8.76 | length 109
  Top Layer w0.2: U8.76@124.745,164.141 124.745,165.218 127.197,167.67 130.988,167.67 132.75,165.907 141.092,165.907 143.002,167.818 143.002,185.139 151.384,193.521 P22.1@151.384,196.088 ; v1(164.948,196.088) 172.069,188.967 172.069,170.291 170.069,168.291 170.069,167.04 171.196,165.913 P23.13@171.196,158.496
  Bottom Layer w0.2: P22.1@151.384,196.088 v1(164.948,196.088)
TMS: P22.3 P23.7 R34.1 U8.78 | length 139.1
  Top Layer w0.2: U8.78@123.745,164.141 123.745,169.647 123.393,169.998 123.393,173.533 123.8,173.939 124.968,173.939 125.781,173.126 125.781,171.78 126.39,171.171 134.925,171.171 138.709,167.386 140.741,167.386 141.199,167.843 141.199,188.646 139.802,190.043 139.802,196.85 140.614,197.663 144.729,197.663 P22.3@146.304,196.088 ; v1(172.491,197.815) 172.491,168.935 R34.1@171.069,167.513 178.816,159.766 P23.7@178.816,158.496
  Bottom Layer w0.2: P22.3@146.304,196.088 148.031,197.815 153.992,197.815 154.991,196.817 157.591,196.817 158.589,197.815 v1(172.491,197.815)
TST: P17.8 P27.2 U8.58 | length 92.1
  Top Layer w0.2: U8.58@126.295,154.091 128.771,154.091 130.08,152.782 v1(131.597,152.782)
  Bottom Layer w0.2: P27.2@124.46,179.959 125.527,178.892 125.527,160.934 124.46,159.868 122.225,159.868 120.603,158.246 120.603,157.63 119.159,156.185 119.159,154.026 119.701,153.483 131.597,153.483 150.809,153.483 150.809,152.782 ; v1(131.597,152.782) 150.809,152.782 ; P17.8@153.924,150.368 151.51,152.782 150.809,152.782
VCC: C2.1 C14.2 C15.2 J4.1 P1.1 P2.1 P5.1 P7.1 P10.2 P11.2 P18.3 P19.15 P20.1 P23.1 P23.2 P24.2 P31.1 P32.2 P34.1 R9.1 R16.2 R27.2 R33.2 R34.2 R35.2 R36.2 R37.2 R38.2 S5.2 S6.2 S7.2 S8.2 U2.2 U8.8 U8.17 U8.33 U8.48 U8.61 U8.84 U8.95 U9.16 U10.3 | length 836.3
  Top Layer w0.2: J4.1@66.953,191.663 69.088,193.798 S5.2@69.088,208.28 69.088,212.598 69.596,213.106 S6.2@69.596,216.916 ; P24.2@88.138,121.031 88.443,121.031 88.443,101.524 R9.1@83.947,97.028 83.947,90.297 U2.2@86.36,87.884 90.464,83.78 C2.1@90.464,79.248 ; P5.1@95.885,240.284 98.933,237.236 98.933,213.233 ; P19.15@98.933,210.185 98.933,213.233 ; P1.1@104.521,218.821 98.933,213.233 ; P7.1@108.712,121.412 108.712,128.896 109.474,129.658 109.474,140.416 114.009,144.951 114.009,145.534 116.245,147.77 U8.33@116.245,149.041 116.245,151.83 115.699,152.376 115.699,154.866 116.23,155.397 116.544,155.397 117.448,156.301 117.448,158.496 116.559,159.385 112.573,159.385 ; v1(109.294,199.824) 109.294,185.321 115.216,179.398 ; U8.17@111.195,154.591 109.42,154.591 107.549,152.719 99.854,152.719 97.655,154.918 97.655,157.099 96.107,158.647 96.107,164.398 108.003,176.293 108.003,178.586 108.815,179.398 115.216,179.398 ; U8.8@111.195,159.091 112.279,159.091 112.573,159.385 ; v1(115.494,170.028) v1@115.245,169.779 ; v1(116.129,160.934) 114.122,160.934 112.573,159.385 ; v1(119.761,160.934) 120.745,161.918 U8.84@120.745,164.141 ; U8.48@123.745,149.041 123.745,143.322 127.259,139.808 127.259,131.555 127.457,131.358 127.457,129.007 128.575,127.889 128.575,110.287 P20.1@127.508,109.22 ; U8.61@126.295,155.591 129.866,155.591 130.501,154.956 135.22,154.956 v1(139.725,159.461) ; P34.1@143.129,211.201 142.062,212.268 142.062,217.406 141.409,218.059 P32.2@139.7,218.059 141.605,219.964 141.605,236.22 P31.1@145.288,239.903 ; v1(164.541,164.744) 170.053,159.233 ; R34.2@171.069,175.133 169.669,173.733 169.669,166.497 170.053,166.113 170.053,159.233 ; U9.16@174.117,109.093 174.117,138.557 P11.2@172.847,139.827 171.729,140.945 171.729,151.384 170.053,153.06 170.053,159.233 ; R36.2@182.753,175.133 181.737,174.117 181.737,162.585 182.829,161.493 182.829,155.346 183.286,154.889 185.369,154.889 P23.2@186.436,155.956 P23.1@186.436,158.496 ; 115.216,179.398 115.245,179.37 115.245,170.028 v1@115.245,169.779 ; 115.216,179.398 115.234,170.027 U8.95@115.245,164.141 v1@115.245,169.779
  Bottom Layer w0.2: S7.2@54.356,208.28 55.601,207.035 67.843,207.035 S5.2@69.088,208.28 ; S6.2@69.596,216.916 71.12,216.916 73.431,219.227 ; C15.2@76.668,79.248 77.684,80.264 89.448,80.264 C2.1@90.464,79.248 93.726,79.248 R16.2@97.282,82.804 ; S8.2@82.804,228.6 73.431,219.227 ; P24.2@88.138,121.031 91.394,124.287 105.837,124.287 P7.1@108.712,121.412 114.757,115.367 128.016,115.367 128.575,114.808 128.575,113.792 128.016,113.233 127.102,113.233 126.446,112.577 126.446,110.282 P20.1@127.508,109.22 135.89,100.838 R27.2@137.668,100.838 139.319,102.489 139.954,102.489 U10.3@142.875,105.41 144.145,104.14 152.4,104.14 P18.3@153.543,105.283 169.113,105.283 170.307,106.477 P10.2@170.307,109.347 172.085,109.347 172.339,109.093 U9.16@174.117,109.093 175.935,107.275 C14.2@195.707,107.275 ; P19.15@98.933,210.185 98.933,207.924 107.033,199.824 v1(109.294,199.824) ; v1(115.494,170.028) 115.494,165.202 v1(119.761,160.934) v1(116.129,160.934) ; P2.1@133.35,239.776 135.306,237.82 143.205,237.82 P31.1@145.288,239.903 146.05,239.141 R38.2@149.352,239.141 R37.2@151.892,239.141 ; P32.2@139.7,218.059 105.283,218.059 P1.1@104.521,218.821 99.619,213.919 74.778,213.919 73.431,215.265 73.431,219.227 ; v1(139.725,159.461) 154.483,159.461 154.974,159.952 154.974,163.576 154.432,164.118 153.738,164.118 152.857,164.998 152.857,166.421 153.111,166.675 154.229,166.675 155.524,167.97 161.315,167.97 v1(164.541,164.744) ; R33.2@165.1,175.26 168.021,175.26 168.148,175.133 R34.2@171.069,175.133 R35.2@176.911,175.133 R36.2@182.753,175.133
VDDCORE: C16.2 P16.15 P17.12 P21.12 P22.12 U8.7 U8.15 U8.37 U8.62 U8.87 U8.100 | length 189.7
  Top Layer w0.2: v1(97.409,160.299) 97.409,158.358 98.262,157.505 99.212,157.505 100.66,156.058 100.66,155.423 102.54,153.543 106.994,153.543 109.042,155.591 U8.15@111.195,155.591 ; v1(105.736,161.976) 106.914,161.976 109.299,159.591 U8.7@111.195,159.591 112.166,159.591 112.795,160.22 ; U8.100@112.745,164.141 112.745,163.118 112.795,163.068 112.795,160.22 ; P21.12@118.364,130.048 117.509,130.903 117.509,144.88 118.245,145.616 U8.37@118.245,149.041 118.245,150.669 116.099,152.816 116.099,154.459 116.637,154.997 v1@120.466,154.997 ; v1(120.472,154.991) v1@120.466,154.997 ; P22.12@123.444,196.088 119.342,191.986 119.342,181.765 118.868,181.29 118.868,175.857 119.595,175.129 119.595,166.1 119.245,165.75 U8.87@119.245,164.141 119.245,163.17 ; U8.62@126.295,156.091 131.635,156.091 v1(131.801,156.256) ; 112.795,160.22 115.407,162.831 118.907,162.831 119.245,163.17 ; 119.245,163.17 119.245,162.56 117.848,161.163 117.848,157.615 v1@120.466,154.997
  Bottom Layer w0.2: P16.15@87.757,158.115 89.941,160.299 90.477,160.299 ; v1(97.409,160.299) 90.477,160.299 ; v1(105.736,161.976) 104.594,160.835 97.409,160.835 90.477,160.835 90.477,160.299 ; v1(120.472,154.991) 121.003,155.522 121.003,157.909 122.072,158.979 123.114,158.979 125.836,156.256 v1(131.801,156.256) 134.298,156.256 139.7,161.658 C16.2@139.7,163.362 151.09,163.362 P17.12@153.924,160.528
VDDFLASH: P22.20
VDDIN: P16.8
VDDIO: P16.17 P17.11 P21.8 P21.23 P22.9 | length 247.6
  Top Layer w0.2: P16.17@87.757,153.035 89.224,154.502 89.224,165.97 88.189,167.005 87.224,167.005 86.707,167.522 86.707,169.079 87.376,169.748 88.748,169.748 89.687,170.688 89.687,187.046 94.234,191.592 94.234,197.053 v1(92.608,198.679) ; v1(108.153,137.008) 108.204,136.957 P21.8@108.204,130.048 ; P21.23@146.304,130.048 146.304,152.552 147.75,153.998 154.88,153.998 155.374,154.492 155.374,156.538 P17.11@153.924,157.988
  Bottom Layer w0.2: P16.17@87.757,153.035 97.536,153.035 97.807,152.764 115.308,152.764 115.392,152.679 115.392,144.247 v1(108.153,137.008) ; v1(92.608,198.679) 93.163,198.124 139.112,198.124 139.751,197.485 139.751,193.777 138.303,192.329 131.267,192.329 130.454,193.142 130.454,195.478 P22.9@131.064,196.088 ; P21.8@108.204,130.048 109.271,131.115 129.24,131.115 129.635,131.51 131.828,131.51 132.216,131.898 145.812,131.898 146.304,131.406 P21.23@146.304,130.048
VDDOUT: P16.7
VDDPLL: P22.25
VIN: C3.1 D4.3 R14.1 U2.3 U3.1 U5.1 U7.1 | length 107.9
  Top Layer w0.2: U3.1@55.88,88.9 53.975,90.805 R14.1@53.975,97.536 55.22,98.781 55.22,130.15 C3.1@56.642,131.572 56.642,144.526 D4.3@58.42,146.304
  Bottom Layer w0.2: U3.1@55.88,88.9 58.115,91.135 66.853,91.135 U5.1@69.596,88.392 72.492,91.288 85.496,91.288 U2.3@88.9,87.884 U7.1@99.06,87.884
XIN/PGMCK: C7.2 P22.22 U8.97 Y1.1 | length 44.2
  Top Layer w0.2: P22.22@98.044,196.088 99.849,194.283 Y1.1@99.849,186.055 104.989,180.915 C7.2@104.989,177.419 ; v1(113.432,177.419) 113.432,167.844 114.245,167.031 U8.97@114.245,164.141
  Bottom Layer w0.2: C7.2@104.989,177.419 105.756,178.186 112.666,178.186 v1(113.432,177.419)
XOUT: C8.2 P22.23 U8.98 Y1.3 | length 48.4
  Top Layer w0.2: C8.2@92.369,177.419 94.969,180.019 Y1.3@94.969,186.055 95.504,186.59 P22.23@95.504,196.088 ; v1(111.573,168.478) 112.148,168.478 113.745,166.881 U8.98@113.745,164.141
  Bottom Layer w0.2: C8.2@92.369,177.419 100.162,169.626 110.426,169.626 v1(111.573,168.478)
pads on no net: J1.1 J1.4 J1.6 J1.7 J1.8 J1.9 J2.1 J2.3 J2.4 J2.5 J3.1 J3.4 J3.6 J3.7 J3.8 J3.9 P4.7 P4.8 P4.9 P4.10 P22.16 P23.17 P23.19 U4.3 U4.4 U4.5 U10.5

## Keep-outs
Keep-Out Layer:
  lines w0.3: 50.844,76.454 210.058,76.454 210.058,243.713 ; 51,76.4 51,243.84 210.185,243.84

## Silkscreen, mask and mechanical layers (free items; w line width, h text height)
Drill Drawing:
  text ".LEGEND" at 255.88,81.28 h1.52
  text "Drill Drawing." at 255.88,78.74 h1.52

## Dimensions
51,76.4 to 51,243.84 on Mechanical 1
50.844,76.454 to 218.44,75.946 on Mechanical 1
